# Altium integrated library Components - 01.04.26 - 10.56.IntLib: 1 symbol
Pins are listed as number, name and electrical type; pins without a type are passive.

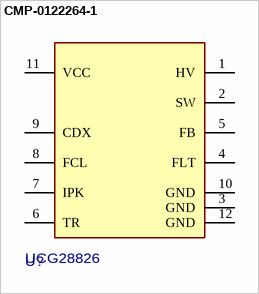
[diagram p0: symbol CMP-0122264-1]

## CMP-0122264-1
designator U?, comment UCG28826
Manufacturer: Texas Instruments; SizeZ_mm: 1mm; AEC Qualified: No; AEC Grade: NA; Standoff Height: 0mm
footprint REZ0012A-MFG
pins: 1 HV (power), 2 SW (power), 3 GND (power), 4 FLT, 5 FB, 6 TR, 7 IPK, 8 FCL, 9 CDX, 10 GND (power), 11 VCC (power), 12 GND (power)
